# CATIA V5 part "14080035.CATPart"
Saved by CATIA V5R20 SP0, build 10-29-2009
Part number: 14080035
Definition: NONE
Nomenclature: 14080035
Source: Unknown
Description: 14080035
Bounding box of the stored display mesh (mm): x -17.5 to 70, y -54 to 43.912, z -44.1 to 44.1
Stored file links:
  C:\Users\Utente\Desktop\IO LAVORO\3D X SITO CF\X SITO\PLASTICA\RF2\14080035.CATPart
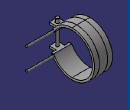
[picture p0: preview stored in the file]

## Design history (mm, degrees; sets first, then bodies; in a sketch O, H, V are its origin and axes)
Body1 "14080035" (main body)
  Solid1: solid without history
